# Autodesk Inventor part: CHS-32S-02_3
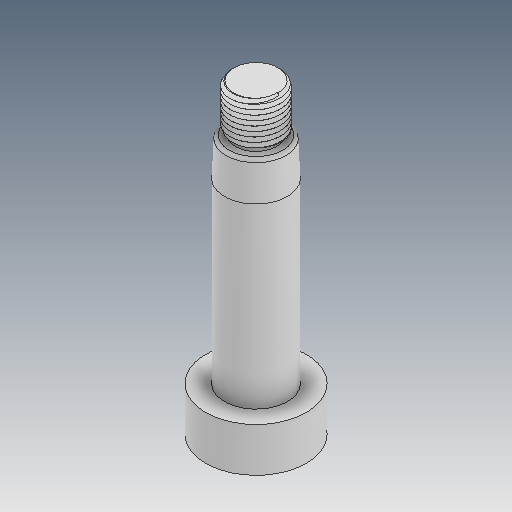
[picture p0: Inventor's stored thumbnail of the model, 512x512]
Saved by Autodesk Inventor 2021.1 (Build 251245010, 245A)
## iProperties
Created: 2021-05
Part Number: CHS-32S-02_3
Material: Ogólny
Document SubType Name: Modeling
Designer: user
Density: 1 g/cm^3
Appearance: Domyślna
Author: user
Revision Number: ÈÎºÎ
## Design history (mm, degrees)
feature "ÊäÈë1"
feature "ÊäÈë2"
node "Bryła1"
node "Bryła2"
